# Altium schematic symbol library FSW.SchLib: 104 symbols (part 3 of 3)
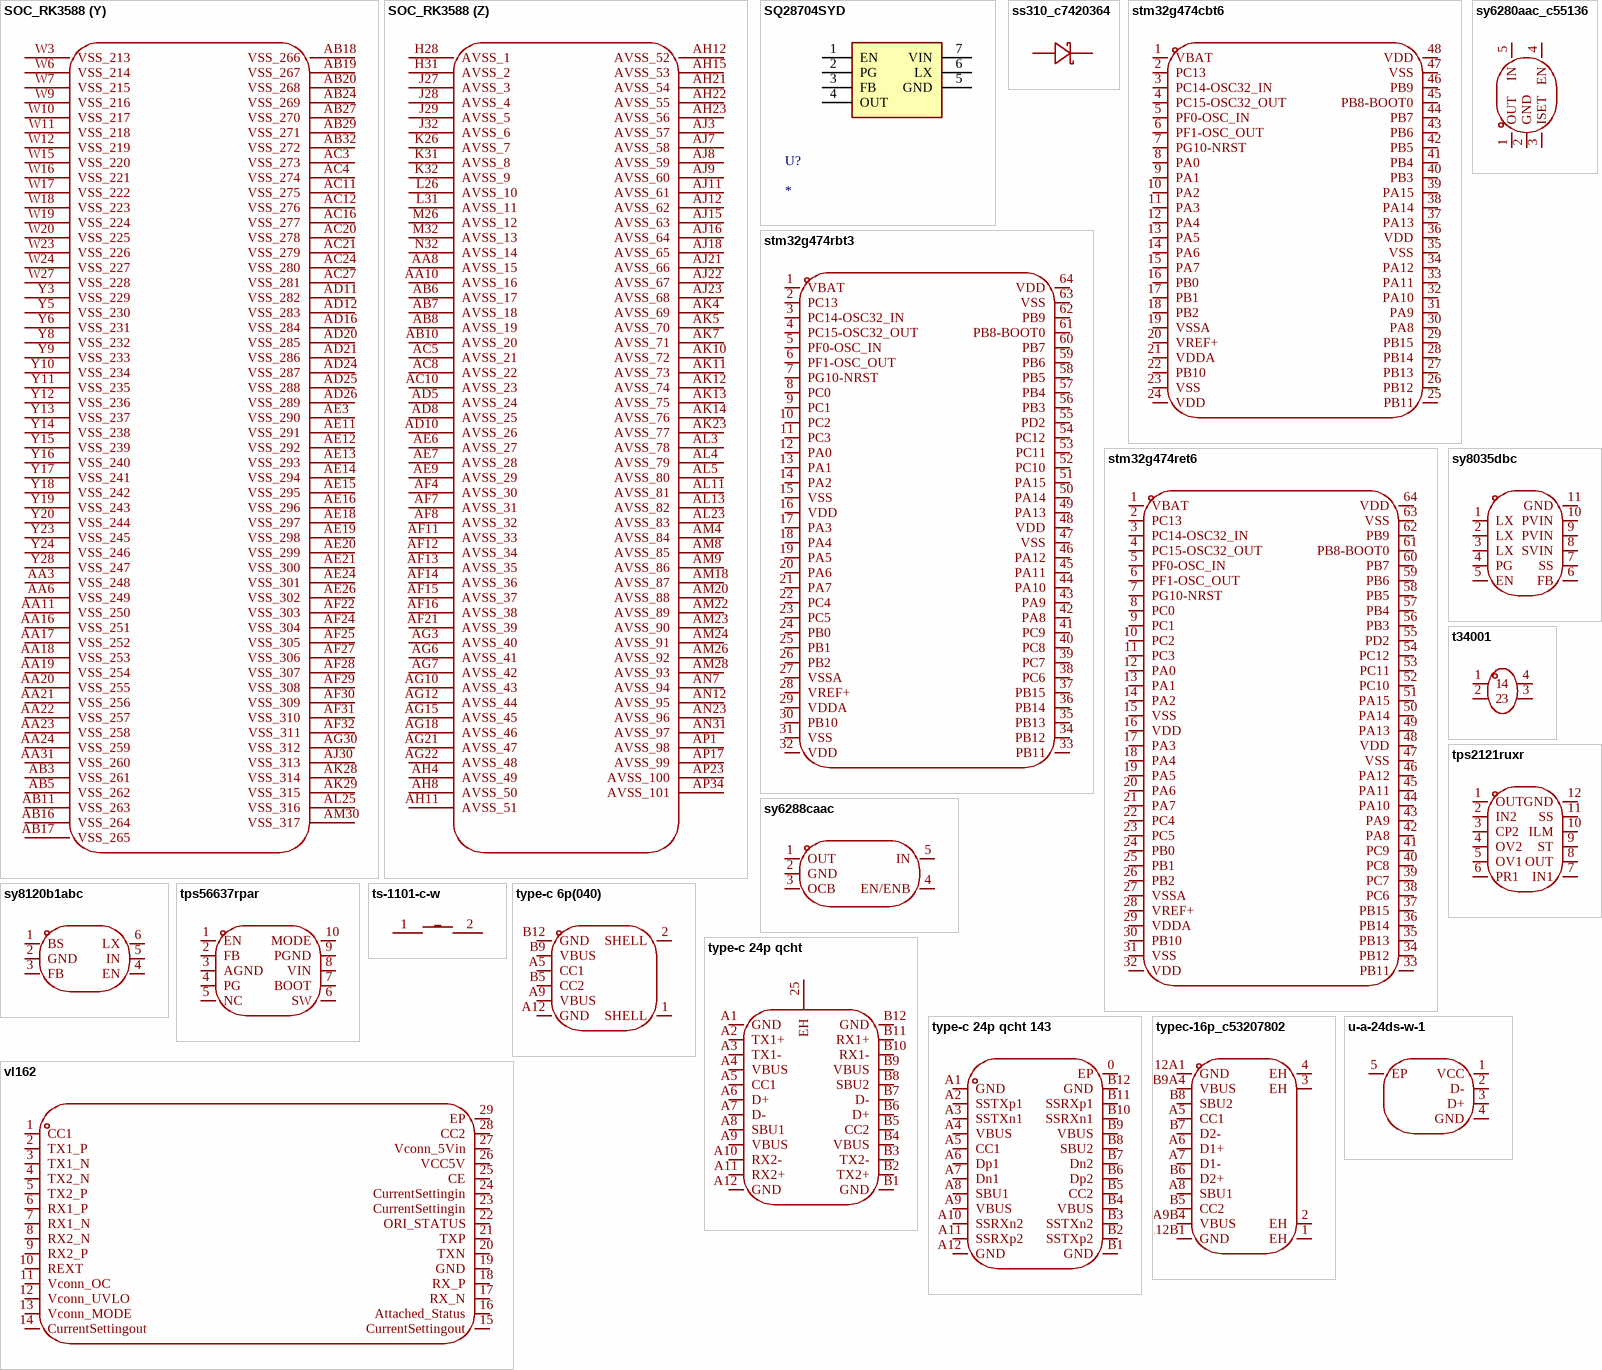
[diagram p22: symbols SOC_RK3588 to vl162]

## stm32g474ret6
designator U??  (value not drawn)
CPU内核:ARM-M4;CPU最大主频:170MHz;应用领域:-;; Manufacturer: ST(意法半导体); AddInBom: yes; ModelId: cd9de06618c44fcf82654c43a457f83c; ModelName: LQFP-64_L10.0-W10.0-H1.4-LS12.0-P0.50; ModelTransform: 472.441,472.441,0,0,0,0,0,0.465,0; CPU Core: ARM-M4; CPU Maximum Speed: 170MHz; Program Storage Size: 512KB; Program Memory Type: FLASH; Number of I/O: 52; ADC (Bit): 12bit; Voltage - Supply: 1.71V~3.6V
footprint LQFP-64_L10.0-W10.0-P0.50-LS12.0-BL
pins: 1 VBAT, 2 PC13, 3 PC14-OSC32_IN, 4 PC15-OSC32_OUT, 5 PF0-OSC_IN, 6 PF1-OSC_OUT, 7 PG10-NRST, 8 PC0, 9 PC1, 10 PC2, 11 PC3, 12 PA0, 13 PA1, 14 PA2, 15 VSS, 16 VDD, 17 PA3, 18 PA4, 19 PA5, 20 PA6, 21 PA7, 22 PC4, 23 PC5, 24 PB0, 25 PB1, 26 PB2, 27 VSSA, 28 VREF+, 29 VDDA, 30 PB10, 31 VSS, 32 VDD, 33 PB11, 34 PB12, 35 PB13, 36 PB14, 37 PB15, 38 PC6, 39 PC7, 40 PC8, 41 PC9, 42 PA8, 43 PA9, 44 PA10, 45 PA11, 46 PA12, 47 VSS, 48 VDD, 49 PA13, 50 PA14, 51 PA15, 52 PC10, 53 PC11, 54 PC12, 55 PD2, 56 PB3, 57 PB4, 58 PB5, 59 PB6, 60 PB7, 61 PB8-BOOT0, 62 PB9, 63 VSS, 64 VDD

## sy6280aac_c55136
designator U??  (value not drawn)
类型:高侧开关;通道数:1;输入控制逻辑:高电平有效;工作电压:2.4V~5.5V;最大连续电流:2A;导通电阻:80mΩ;; Manufacturer: Silergy(矽力杰); AddInBom: yes; ModelId: 0a2a1b8f50944f73965918ad6e5fe167; ModelName: SOT-23-5_L2.9-W1.6-H1.1-LS2.8-P0.95; ModelTransform: 118.60433,114.173,0,90,0,0,0.0005,0.0005,0; Number of Channels: 1; Control Input Logic: 高电平有效; Maximum Continuous Current: 2A; RDS(on): 80mΩ
footprint SOT-23-5_L3.0-W1.7-P0.95-LS2.8-BL
pins: 1 OUT, 2 GND, 3 ISET, 4 EN, 5 IN

## sy6288caac
designator U??  (value not drawn)
类型:负载开关;通道数:1;输入控制逻辑:高电平有效;工作电压:2.5V~5.5V;最大连续电流:2A;导通电阻:60mΩ;; Manufacturer: Silergy(矽力杰); AddInBom: yes; ModelId: 0a2a1b8f50944f73965918ad6e5fe167; ModelName: SOT-23-5_L2.9-W1.6-H1.1-LS2.8-P0.95; ModelTransform: 114.173,109.636,0,180,0,0,0,0,0; Number of Channels: 1; Control Input Logic: 高电平有效; Maximum Continuous Current: 2A; RDS(on): 60mΩ
footprint SOT-23-5_L3.0-W1.7-P0.95-LS2.8-BR
pins: 1 OUT, 2 GND, 3 OCB, 4 EN/ENB, 5 IN

## sy8035dbc
designator U??  (value not drawn)
功能类型:降压型;工作电压:2.7V~5.5V;输出电压:600mV~5.5V;输出电流:5A;输出类型:可调;; Manufacturer: Silergy(矽力杰); AddInBom: yes; ModelId: f2c5a86f900941fe8fc94a62166302e6; ModelName: TDFN-10_L3.0-W3.0-H0.8-P0.50; ModelTransform: 118.11,118.8974,0,0,0,0,0,-0.0005,0; Function: 降压型; Output Current: 5A; Frequency - Switching: 1MHz; Synchronous Rectifier: 是; Number of Outputs: 1; Topology: 降压式; Quiescent Current: 150uA; Switch tube (built-in/external): 内置; Output Type: 可调
footprint TDFN-10_L3.0-W3.0-P0.50-BL-EP
pins: 1 LX, 2 LX, 3 LX, 4 PG, 5 EN, 6 FB, 7 SS, 8 SVIN, 9 PVIN, 10 PVIN, 11 GND

## sy8120b1abc
designator U??  (value not drawn)
功能类型:降压型;工作电压:4.5V~18V;输出电压:-;输出电流:2A;输出类型:可调;; Manufacturer: Silergy(矽力杰); AddInBom: yes; ModelId: 18da8f6c14a34920b3e136b5c401a119; ModelName: SOT-23-6_L2.9-W1.6-H1.5-LS2.8-P0.95; ModelTransform: 110.236,113.364,0,90,0,0,0.0005,0.0005,0; Function: 降压型; Output Current: 2A; Frequency - Switching: 500kHz; Synchronous Rectifier: 是; Number of Outputs: 1; Topology: 降压式; Quiescent Current: 400uA; Switch tube (built-in/external): 内置; Output Type: 可调
footprint SOT-23-6_L2.9-W1.6-P0.95-LS2.8-BL
pins: 1 BS, 2 GND, 3 FB, 4 EN, 5 IN, 6 LX

## t34001
designator U??  (value not drawn)
Manufacturer: XFCN(兴飞); AddInBom: yes; ModelId: 9a18b4251ffd4ebd840028391c6881d2; ModelName: CONN-TH_T34001; ModelTransform: 314.96,314.96,0,0,0,0,0,0,-118.11
footprint CONN-TH_T34001
pins: 1, 2, 3, 4

## tps2121ruxr
designator U??  (value not drawn)
TPS2121 支持无缝切换的 2.7V 至 22V、56mΩ、4.5A 电源多路复用器; Manufacturer: TI(德州仪器); AddInBom: yes; ModelId: 23ed45b0241644698956addf625daed0; ModelName: VQFN-HR-12_L2.5-W2.0-H1.0-P0.50-BL; ModelTransform: 78.74,98.425,0,90,0,0,-0.004,0.002,0
footprint VQFN-HR-12_L2.5-W2.0-P0.50-BL
pins: 1 OUT, 2 IN2, 3 CP2, 4 OV2, 5 OV1, 6 PR1, 7 IN1, 8 OUT, 9 ST, 10 ILM, 11 SS, 12 GND

## tps56637rpar
designator U??  (value not drawn)
功能类型:降压型;输出类型:可调;输入电压:4.5V~28V;输出电压:600mV~13V;输出电流(最大值):6A;; Manufacturer: TI(德州仪器); AddInBom: yes; ModelId: 5db67d97db7a4d23a493647eeeda17db; ModelName: VQFN-HR-10_L3.0-W3.0_RPA; ModelTransform: 118.8974,118.8974,0,0,0,0,1.575,0,0; Function: 降压型; Output Type: 可调; Output Current (Max): 6A; Switching Frequency: 500kHz; Synchronous Rectification: 是; Number of Outputs: 1; Topology: 降压式; Switch tube (built-in/external): 内置
footprint VQFN-HR-10_L3.0-W3.0_RPA
pins: 1 EN, 2 FB, 3 AGND, 4 PG, 5 NC, 6 SW, 7 BOOT, 8 VIN, 9 PGND, 10 MODE

## ts-1101-c-w
designator SW??  (value not drawn)
电路结构:单刀单掷;按钮形状:矩形按钮;作用力:2.6N;安装方式:立贴;开关长度:6mm;开关宽度:3.6mm;开关高度:2.5mm;带支架:不带支架;触点电流:50mA;额定电压:12V;带灯:无;工作寿命:5万次;; Manufacturer: XKB Connection(中国星坤); AddInBom: yes; ModelId: 0fd6340cfb7d45bfbbb5f8576d023f85; ModelName: SW-SMD_L6.0-W3.3-LS8.0_TS-1101-C-W; ModelTransform: 315.232,145.669,0,0,0,0,0,0,0; Circuit: 单刀单掷; Actuator Style: 矩形按钮; Operating Force: 2.6N; Switch Height: 2.5mm; with Bracket: 不带支架; Contact Current: 50mA; Voltage Rating: 12V; With Lamp: 无; Life: 5万次
footprint SW-SMD_L6.0-W3.3-LS8.0_TS-1101-C-W
pins: 1, 2

## type-c 6p(040)
designator USB??  (value not drawn)
连接器类型:Type-C;协议标准:USB 3.1;公母:母;安装方式:卧贴;触点数量:6P;端口数量:1;额定电流 - 电源:3A;工作温度:-30℃~+80℃;; Manufacturer: SHOU HAN(首韩); AddInBom: yes; SymbolName: TYPE-C 6P(040新); ModelId: fb1418f8b16e47cdb24a4fea470b26a0; ModelName: USB-C-SMD_TYPE-C-6P; ModelTransform: 351.9678,267.716,0,0,0,0,0,-43.189,-39.37; Protocol Standard: USB 3.1; Gender: 母; Number of Ports: 1; Current Rating-Power: 3A; Voltage Rating: 5V; Connect-Disconnect Life: 3千次; Detection color: 黑色
footprint USB-C-SMD_TYPE-C-6P
pins: 1 SHELL, 2 SHELL, A5 CC1, A9 VBUS, A12 GND, B5 CC2, B9 VBUS, B12 GND

## type-c 24p qcht
designator USB??  (value not drawn)
连接器类型:Type-C;协议标准:USB 3.1;公母:母;安装方式:卧贴;触点数量:24P;端口数量:1;额定电流 - 电源:3A;工作温度:-40℃~+85℃;; Manufacturer: SHOU HAN(首韩); AddInBom: yes; ModelId: caecbdeb99a8472ba4a8af874d656e7a; ModelName: TYPE-C-SMD_TYPE-C-24P-QCHT; ModelTransform: 379.5268,387.7945,0,0,0,0,0,-30.041,-47.244; Protocol Standard: USB 3.1; Gender: 母; Number of Ports: 1; Current Rating-Power: 3A; Voltage Rating: 30V; Connect-Disconnect Life: 1万次; Detection color: 黑色
footprint TYPE-C-SMD_TYPE-C-24P-QCHT
pins: 25 EH, A1 GND, A2 TX1+, A3 TX1-, A4 VBUS, A5 CC1, A6 D+, A7 D-, A8 SBU1, A9 VBUS, A10 RX2-, A11 RX2+, A12 GND, B1 GND, B2 TX2+, B3 TX2-, B4 VBUS, B5 CC2, B6 D+, B7 D-, B8 SBU2, B9 VBUS, B10 RX1-, B11 RX1+, B12 GND

## type-c 24p qcht 143
designator U??  (value not drawn)
连接器类型:Type-C;协议标准:USB 3.1;公母:母;安装方式:卧贴;触点数量:24P;端口数量:1;额定电流 - 电源:5A;工作温度:-30℃~+85℃;; Manufacturer: SHOU HAN(首韩); AddInBom: yes; ModelId: eaa4b9b3afc14d249fd710642c6ba1be; ModelName: TYPE-C-USB-SMD_QCHT-143; ModelTransform: 397.637,388.582,0,0,0,0,-0.039,-27.519,-47.244; Protocol Standard: USB 3.1; Gender: 母; Number of Ports: 1; Current Rating-Power: 5A; Connect-Disconnect Life: 1万次; Detection color: 黑色
footprint TYPE-C-USB-SMD_QCHT-143
pins: 0 EP, A1 GND, A2 SSTXp1, A3 SSTXn1, A4 VBUS, A5 CC1, A6 Dp1, A7 Dn1, A8 SBU1, A9 VBUS, A10 SSRXn2, A11 SSRXp2, A12 GND, B1 GND, B2 SSTXp2, B3 SSTXn2, B4 VBUS, B5 CC2, B6 Dp2, B7 Dn2, B8 SBU2, B9 VBUS, B10 SSRXn1, B11 SSRXp1, B12 GND

## typec-16p_c53207802
designator USB??  (value not drawn)
连接器类型:Type-C;协议标准:-;公母:母;安装方式:卧贴;触点数量:16P;端口数量:1;额定电流 - 电源:3A;工作温度:-40℃~+85℃;; Manufacturer: JXTCONN(聚兴泰); AddInBom: yes; ModelId: 52ede7ec195f4cdf9ab9a781197ce986; ModelName: USB-C-SMD_TYPEC-16P_C53207802; ModelTransform: 351.9678,301.181,0,0,0,0,0,-43.307,-43.307; Connector Type: Type-C; Gender: 母; Number of Contacts: 16P; Number of Ports: 1; Current Rating-Power: 3A; Voltage Rating: 20V; Connect-Disconnect Life: 1万次; Detection color: 黑色
footprint USB-C-SMD_TYPEC-16P_C53207802
pins: 1 EH, 2 EH, 3 EH, 4 EH, A5 CC1, A6 D1+, A7 D1-, A8 SBU1, A9B4 VBUS, A12B1 GND, B5 CC2, B6 D2+, B7 D2-, B8 SBU2, B9A4 VBUS, B12A1 GND

## u-a-24ds-w-1
designator USB??  (value not drawn)
连接器类型:Type-A;协议标准:USB 2.0;公母:母;安装方式:沉板;触点数量:4P;端口数量:1;额定电流 - 电源:1.5A;工作温度:-40℃~+85℃;; Manufacturer: 韩国韩荣; AddInBom: yes; ModelId: 30cd27839acf44a796789f77f974bdc7; ModelName: USB-A-SMD_U-A-24DS-W-1; ModelTransform: 624.0145,492.125,0,0,0,0,0,-90.88,-70.866; Connector Type: Type-A; Protocol Standard: USB 2.0; Gender: 母; Number of Contacts: 4P; Number of Ports: 1; Current Rating-Power: 1.5A; Connect-Disconnect Life: 5千次
footprint USB-A-SMD_U-A-24DS-W-2
pins: 1 VCC, 2 D-, 3 D+, 4 GND, 5 EP

## vl162
designator U??  (value not drawn)
特性：USB Type-C数据开关，带适用于USB 3.1 Gen2 (10 Gbps)的CC功能。 4:2 10Gbps USB Type-C数据开关。 支持高达10Gbps。应用：线缆+设备应用; Manufacturer: VIA Labs(威锋电子); AddInBom: yes; ModelId: b29b69759c5e47d881066d3712682f60; ModelName: MQFN-28_L4.5-W3.5-P0.40-BL-EP; ModelTransform: 177.952,138.5824,0,0,0,0,0,0,0; USB Protocol: USB 3.1; Voltage - Supply: 4.5V~5.5V; Current - Supply: 1.2mA; Quiescent Supply Current: 0.5mA; Number of Channels: 2
footprint MQFN-28_L4.5-W3.5-P0.40-BL-EP
pins: 1 CC1, 2 TX1_P, 3 TX1_N, 4 TX2_N, 5 TX2_P, 6 RX1_P, 7 RX1_N, 8 RX2_N, 9 RX2_P, 10 REXT, 11 Vconn_OC, 12 Vconn_UVLO, 13 Vconn_MODE, 14 CurrentSettingout, 15 CurrentSettingout, 16 Attached_Status, 17 RX_N, 18 RX_P, 19 GND, 20 TXN, 21 TXP, 22 ORI_STATUS, 23 CurrentSettingin, 24 CurrentSettingin, 25 CE, 26 VCC5V, 27 Vconn_5Vin, 28 CC2, 29 EP

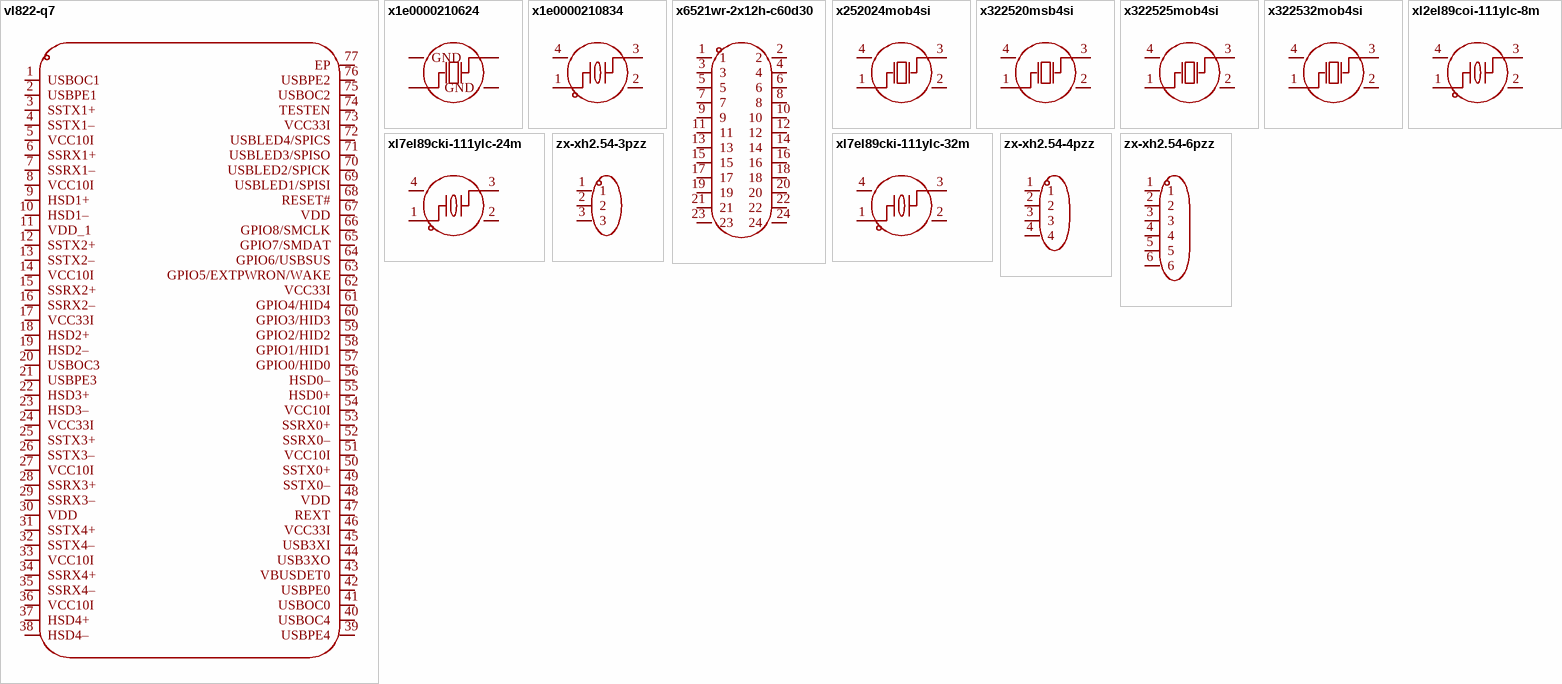
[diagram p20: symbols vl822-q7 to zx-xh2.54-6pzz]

## vl822-q7
designator U??  (value not drawn)
VL822是一款USB 3.1 Gen2集线器控制器，具有高度集成的专用应用设计。VL822有1个上游端口和4个/2个下游端口，所有端口均支持10Gbps的USB 3.1 Gen2操作。下游端口可支持超速+（10Gbps）、超速（5Gbps）、高速（480Mbps）、全速（12Mbps）和低速（1.5Mbps）设备的任意组合; Manufacturer: VIA Labs(威锋电子); AddInBom: yes; ModelId: cfb2f5f80e274f87b1df67cc6bc46959; ModelName: QFN-76_L9.0-W9.0-H0.9-P0.40-EP6.4-TL; ModelTransform: 354.33,354.33,0,0,0,0,0,0,0; USB Protocol: USB 3.1；USB 2.0; Data Rate: 480Mbps；10Gbps; Voltage - Supply: 0.95V~1.05V；3V~3.6V; Memory Interface: SPI; Number of Channels: 4
footprint QFN-76_L9.0-W9.0-P0.40-EP6.3-TL
pins: 1 USBOC1, 2 USBPE1, 3 SSTX1+, 4 SSTX1–, 5 VCC10I, 6 SSRX1+, 7 SSRX1–, 8 VCC10I, 9 HSD1+, 10 HSD1–, 11 VDD_1, 12 SSTX2+, 13 SSTX2–, 14 VCC10I, 15 SSRX2+, 16 SSRX2–, 17 VCC33I, 18 HSD2+, 19 HSD2–, 20 USBOC3, 21 USBPE3, 22 HSD3+, 23 HSD3–, 24 VCC33I, 25 SSTX3+, 26 SSTX3–, 27 VCC10I, 28 SSRX3+, 29 SSRX3–, 30 VDD, 31 SSTX4+, 32 SSTX4–, 33 VCC10I, 34 SSRX4+, 35 SSRX4–, 36 VCC10I, 37 HSD4+, 38 HSD4–, 39 USBPE4, 40 USBOC4, 41 USBOC0, 42 USBPE0, 43 VBUSDET0, 44 USB3XO, 45 USB3XI, 46 VCC33I, 47 REXT, 48 VDD, 49 SSTX0–, 50 SSTX0+, 51 VCC10I, 52 SSRX0–, 53 SSRX0+, 54 VCC10I, 55 HSD0+, 56 HSD0–, 57 GPIO0/HID0, 58 GPIO1/HID1, 59 GPIO2/HID2, 60 GPIO3/HID3, 61 GPIO4/HID4, 62 VCC33I, 63 GPIO5/EXTPWRON/WAKE, 64 GPIO6/USBSUS, 65 GPIO7/SMDAT, 66 GPIO8/SMCLK, 67 VDD, 68 RESET#, 69 USBLED1/SPISI, 70 USBLED2/SPICK, 71 USBLED3/SPISO, 72 USBLED4/SPICS, 73 VCC33I, 74 TESTEN, 75 USBOC2, 76 USBPE2, 77 EP

## x1e0000210624
designator X??  (value not drawn)
晶振类型:贴片晶振;频率:20MHz;常温频差:±10ppm;负载电容:12pF;频率稳定度:±18ppm;; Manufacturer: EPSON(爱普生); AddInBom: yes; ModelId: ff2dfd5650294453a14147960efe1838; ModelName: CRYSTAL-SMD_4P-L3.2-W2.5-BL; ModelTransform: 125.984,98.425,0,0,0,0,0,0,0; Value: 20MHz; Normal temperature Frequency Tolerance: ±10ppm; Load Capacitance: 12pF; Frequency Stability: ±18ppm; Equivalent Series Resistance(ESR): 60Ω
footprint CRYSTAL-SMD_4P-L3.2-W2.5-BL
pins: 1 OSC1, 2 GND, 3 OSC2, 4 GND

## x1e0000210834
designator X??  (value not drawn)
晶振类型:贴片晶振;频率:48MHz;常温频差:±10ppm;负载电容:10pF;频率稳定度:±10ppm;; Manufacturer: EPSON(爱普生); AddInBom: yes; ModelId: ff2dfd5650294453a14147960efe1838; ModelName: CRYSTAL-SMD_4P-L3.2-W2.5-BL; ModelTransform: 125.984,98.425,0,0,0,0,0,0,0; Value: 48MHz; Normal temperature Frequency Tolerance: ±10ppm; Load Capacitance: 10pF; Equivalent Series Resistance(ESR): 40Ω
footprint CRYSTAL-SMD_4P-L3.2-W2.5-BL
pins: 1, 2 GND, 3, 4 GND

## x6521wr-2x12h-c60d30
designator H??  (value not drawn)
插针结构:2x12P;间距:2.54mm;行距:2.54mm;圆针/方针:方针;排数:双排;总PIN位数:24P;额定电流:3A;额定电压:250V;配合针长度:-;塑高:2.5mm;端接针长度:-;触头材质:黄铜;触头镀层:金;工作温度:-40℃~+105℃;颜色:黑色;; Manufacturer: XKB Connection(中国星坤); Symbol: X6521WR-2×12H-C30D60; AddInBom: yes; ModelId: c87603f207fc4d939d696e0588895b6d; ModelName: HDR-TH_24P-P2.54-M-WI-2X12P; ModelTransform: 1199.9976,507.873,0,0,0,0,0,-190.945,-118.11; Pin Structure: 2x12P; Pitch: 2.54mm; Circluar Pins/Square Pins: 方针; Current Rating: 3A; Voltage Rating (Max): 250V
footprint HDR-TH_24P-P2.54-H-M-R2-C12-S2.54
pins: 1, 2, 3, 4, 5, 6, 7, 8, 9, 10, 11, 12, 13, 14, 15, 16, 17, 18, 19, 20, 21, 22, 23, 24

## x252024mob4si
designator X??  (value not drawn)
晶振类型:贴片晶振;频率:24MHz;常温频差:±10ppm;负载电容:12pF;频率稳定度:±20ppm;; Manufacturer: YXC(扬兴晶振); AddInBom: yes; ModelId: d23e0abc26e54c15b6292fd5f43702fa; ModelName: CRYSTAL-SMD_4P-L2.5-W2.0-BL; ModelTransform: 98.425,78.74,0,0,0,0,0,0,0; Value: 24MHz; Normal temperature Frequency Tolerance: ±10ppm; Load Capacitance: 12pF; Frequency Stability: ±20ppm; Equivalent Series Resistance(ESR): 100Ω
footprint CRYSTAL-SMD_4P-L2.5-W2.0-BL
pins: 1 OSC1, 2 GND, 3 OSC2, 4 GND

## x322520msb4si
designator X??  (value not drawn)
晶振类型:贴片晶振;频率:20MHz;常温频差:±10ppm;负载电容:20pF;频率稳定度:±20ppm;; Manufacturer: YXC(扬兴晶振); AddInBom: yes; ModelId: 6000dc8adf4c4082a91df701f77194e1; ModelName: CRYSTAL-SMD_4P-L3.2-W2.5-BL-2; ModelTransform: 125.984,98.425,0,0,0,0,-0.001,0.003,0; Value: 20MHz; Normal temperature Frequency Tolerance: ±10ppm; Load Capacitance: 20pF; Frequency Stability: ±20ppm; Equivalent Series Resistance(ESR): 50Ω
footprint CRYSTAL-SMD_4P-L3.2-W2.5-BL-2
pins: 1 OSC1, 2 GND, 3 OSC2, 4 GND

## x322525mob4si
designator X??  (value not drawn)
晶振类型:贴片晶振;频率:25MHz;常温频差:±10ppm;负载电容:12pF;频率稳定度:±20ppm;; Manufacturer: YXC(扬兴晶振); AddInBom: yes; ModelId: ff2dfd5650294453a14147960efe1838; ModelName: CRYSTAL-SMD_4P-L3.2-W2.5-BL; ModelTransform: 125.984,98.425,0,0,0,0,0,0,0; Value: 25MHz; Normal temperature Frequency Tolerance: ±10ppm; Load Capacitance: 12pF; Frequency Stability: ±20ppm; Equivalent Series Resistance(ESR): 50Ω
footprint CRYSTAL-SMD_4P-L3.2-W2.5-BL
pins: 1 OSC1, 2 GND, 3 OSC2, 4 GND

## x322532mob4si
designator X??  (value not drawn)
晶振类型:贴片晶振;频率:32MHz;常温频差:±10ppm;负载电容:12pF;频率稳定度:±20ppm;; Manufacturer: YXC(扬兴晶振); AddInBom: yes; ModelId: ff2dfd5650294453a14147960efe1838; ModelName: CRYSTAL-SMD_4P-L3.2-W2.5-BL; ModelTransform: 125.984,98.425,0,0,0,0,0,0,0; Value: 32MHz; Normal temperature Frequency Tolerance: ±10ppm; Load Capacitance: 12pF; Frequency Stability: ±20ppm; Equivalent Series Resistance(ESR): 40Ω
footprint CRYSTAL-SMD_4P-L3.2-W2.5-BL
pins: 1 OSC1, 2 GND, 3 OSC2, 4 GND

## xl2el89coi-111ylc-8m
designator X??  (value not drawn)
晶振类型:贴片晶振;频率:8MHz;常温频差:±10ppm;负载电容:12pF;频率稳定度:±20ppm;; Manufacturer: YXC(扬兴晶振); AddInBom: yes; ModelId: 4495b492a02c4f389e505ec8ae3aaf1b; ModelName: CRYSTAL-SMD_4P-L3.2-W2.5-BL-1; ModelTransform: 125.984,98.425,0,0,0,0,0,0,0; Value: 8MHz; Normal temperature Frequency Tolerance: ±10ppm; Load Capacitance: 12pF; Frequency Stability: ±20ppm; Equivalent Series Resistance(ESR): 180Ω
footprint CRYSTAL-SMD_4P-L3.2-W2.5-BL-1
pins: 1, 2 GND, 3, 4 GND

## xl7el89cki-111ylc-24m
designator X??  (value not drawn)
晶振类型:贴片晶振;频率:24MHz;常温频差:±10ppm;负载电容:8pF;频率稳定度:±20ppm;; Manufacturer: YXC(扬兴晶振); AddInBom: yes; ModelId: ff569852e08d42e6a0afc8f1b31cbda0; ModelName: CRYSTAL-SMD_4P-L2.0-W1.6-BL-A; ModelTransform: 78.74,62.992,0,0,0,0,0,0,0; Value: 24MHz; Normal temperature Frequency Tolerance: ±10ppm; Load Capacitance: 8pF; Frequency Stability: ±20ppm; Equivalent Series Resistance(ESR): 100Ω
footprint CRYSTAL-SMD_4P-L2.0-W1.6-BL-A
pins: 1, 2 GND, 3, 4 GND

## xl7el89cki-111ylc-32m
designator X??  (value not drawn)
晶振类型:贴片晶振;频率:32MHz;常温频差:±10ppm;负载电容:8pF;频率稳定度:±20ppm;; Manufacturer: YXC(扬兴晶振); AddInBom: yes; ModelId: 5d2c7f6d96ec4dd1b062bb930f1f4d30; ModelName: CRYSTAL-SMD_4P-L2.0-W1.6-BL; ModelTransform: 80.709,64.961,0,0,0,0,0,0,0; Value: 32MHz; Normal temperature Frequency Tolerance: ±10ppm; Load Capacitance: 8pF; Frequency Stability: ±20ppm; Equivalent Series Resistance(ESR): 80Ω
footprint CRYSTAL-SMD_4P-L2.0-W1.6-BL
pins: 1, 2 GND, 3, 4 GND

## zx-xh2.54-3pzz
designator CN??  (value not drawn)
插针结构:1x3P;间距:2.5mm;安装方式:直插;参考系列:XH;总PIN数:3P;排数:1;每排PIN数:3;行距:-;额定电流:3A;触头材质:黄铜;触头镀层:锡;工作温度:-25℃~+85℃;; Manufacturer: Megastar(兆星); AddInBom: yes; ModelId: 59fb7dae5f784ea68cfa01be7f96d370; ModelName: CONN-TH_3P-P2.54_2501S-3P; ModelTransform: 393.7,224.409,0,0,0,0,0,15.748,-137.795; Pins Structure: 1x3P; Pitch: 2.5mm; Reference Series: XH; Number of PINs Per Row: 3; Current Rating: 3A; Voltage Rating: 250V; Plastic Material: PA66; Flame Retardant Rating: UL94V-0; Z-Height of the Board: 7mm; X-Length of Bottom Edge on Board (Spacing Line): 10mm; Y-Width of Bottom Edge on Board: 5.9mm
footprint CONN-TH_3P-P2.54_2501S-3P
pins: 1, 2, 3

## zx-xh2.54-4pzz
designator CN??  (value not drawn)
插针结构:1x4P;间距:2.5mm;安装方式:直插;参考系列:XH;总PIN数:4P;排数:1;每排PIN数:4;行距:-;额定电流:3A;触头材质:黄铜;触头镀层:锡;工作温度:-25℃~+85℃;; Manufacturer: Megastar(兆星); AddInBom: yes; ModelId: 5458b55d28744a3c82c1e0e5bffe4e87; ModelName: CONN-TH_4P-P2.50_4PIN; ModelTransform: 492.125,224.409,0,180,0,0,0,17.717,-118.11; Pins Structure: 1x4P; Pitch: 2.5mm; Reference Series: XH; Number of PINs Per Row: 4; Current Rating: 3A; Voltage Rating: 250V; Plastic Material: PA66; Flame Retardant Rating: UL94V-0; Z-Height of the Board: 7mm; X-Length of Bottom Edge on Board (Spacing Line): 12.5mm; Y-Width of Bottom Edge on Board: 5.9mm
footprint CONN-TH_4P-P2.50_4PIN
pins: 1, 2, 3, 4

## zx-xh2.54-6pzz
designator U??  (value not drawn)
插针结构:1x6P;间距:2.5mm;安装方式:直插;参考系列:XH;总PIN数:6P;排数:1;每排PIN数:6;行距:-;额定电流:3A;触头材质:黄铜;触头镀层:锡;工作温度:-25℃~+85℃;; Manufacturer: Megastar(兆星); AddInBom: yes; ModelId: 69bbd5a736b94698bef26e8b4cdae04d; ModelName: CONN-TH_6P-P2.50_ZX-XH2.54-6PZZ; ModelTransform: 688.975,232.6767,0,0,0,0,0,14.528,-133.858; Pins Structure: 1x6P; Pitch: 2.5mm; Reference Series: XH; Number of PINs Per Row: 6; Current Rating: 3A; Voltage Rating: 250V; Plastic Material: PA66; Flame Retardant Rating: UL94V-0; Z-Height of the Board: 7mm; X-Length of Bottom Edge on Board (Spacing Line): 17.5mm; Y-Width of Bottom Edge on Board: 5.9mm
footprint CONN-TH_6P-P2.50_ZX-XH2.54-6PZZ
pins: 1, 2, 3, 4, 5, 6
